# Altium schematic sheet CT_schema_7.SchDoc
size 454 x 430 mm
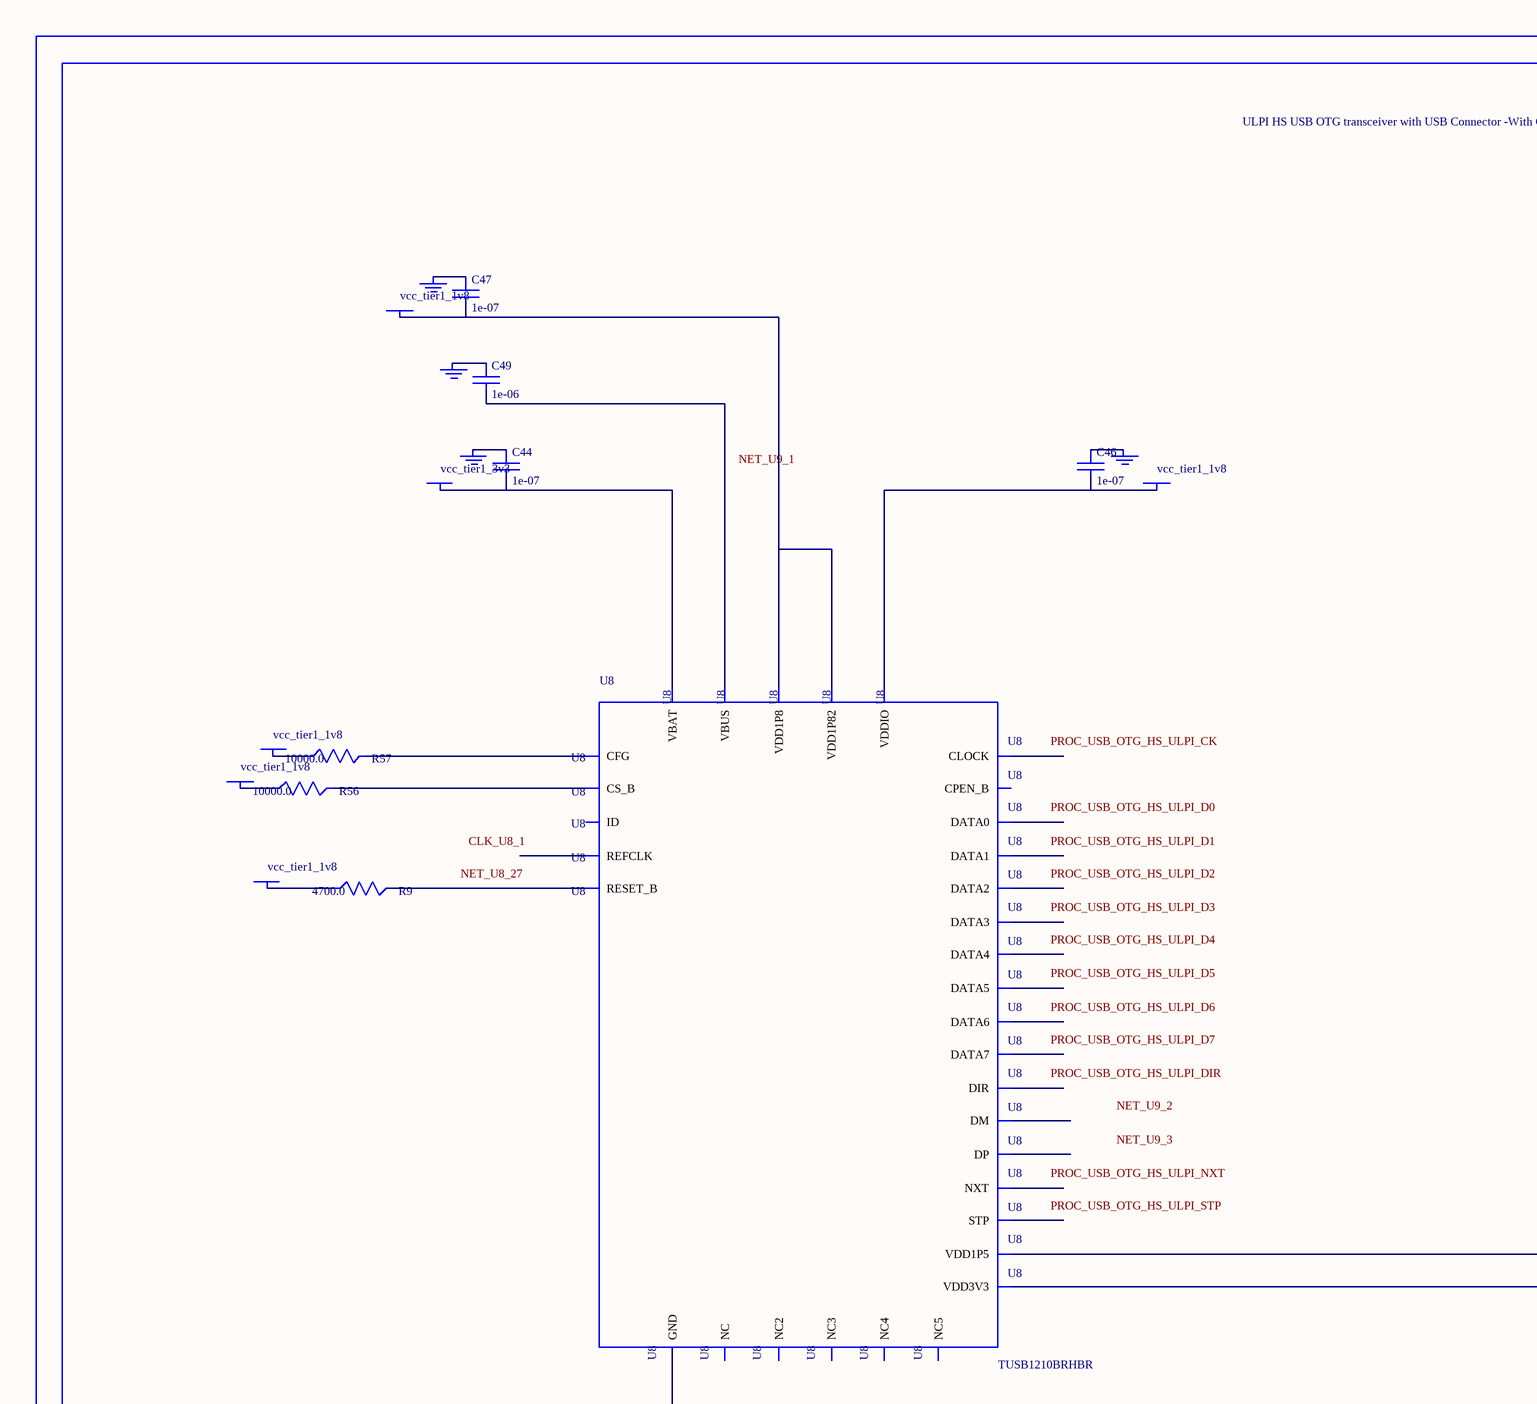
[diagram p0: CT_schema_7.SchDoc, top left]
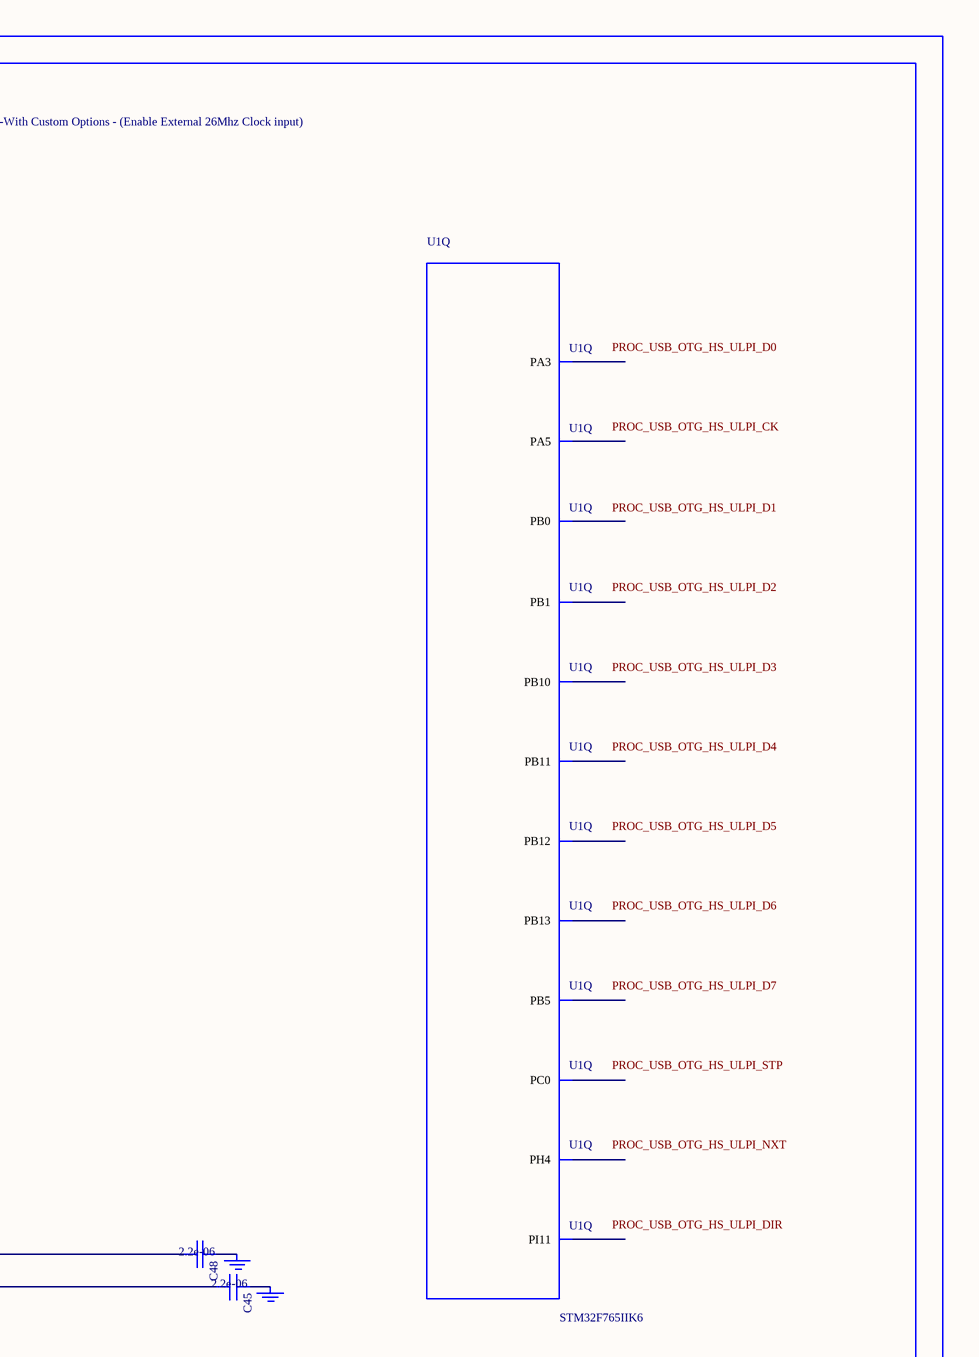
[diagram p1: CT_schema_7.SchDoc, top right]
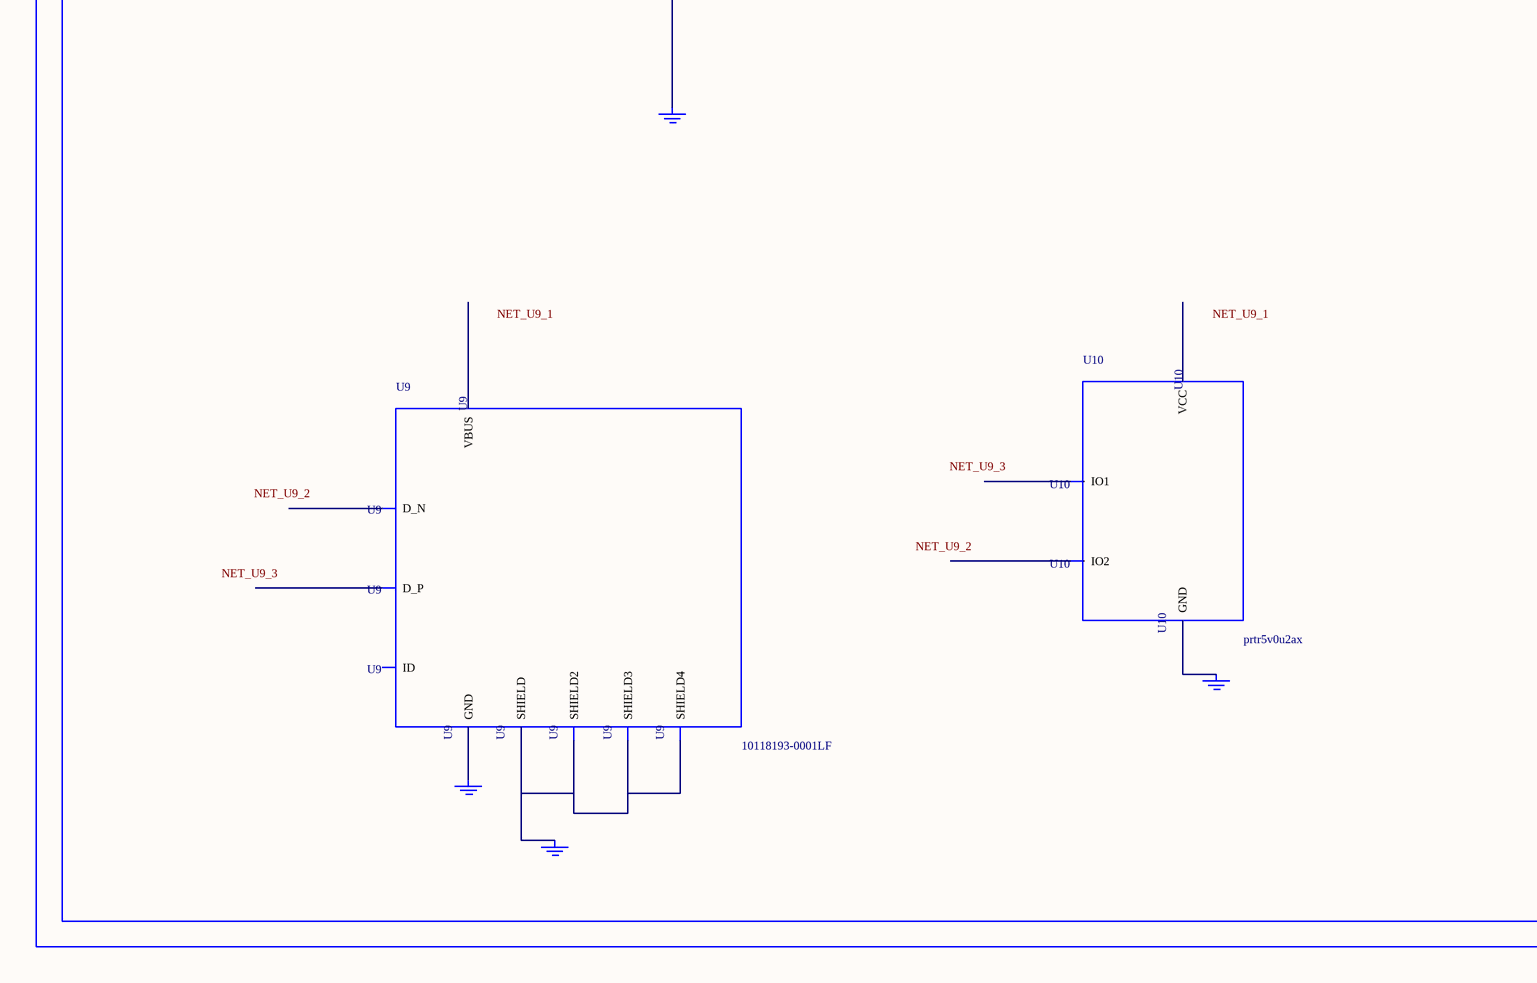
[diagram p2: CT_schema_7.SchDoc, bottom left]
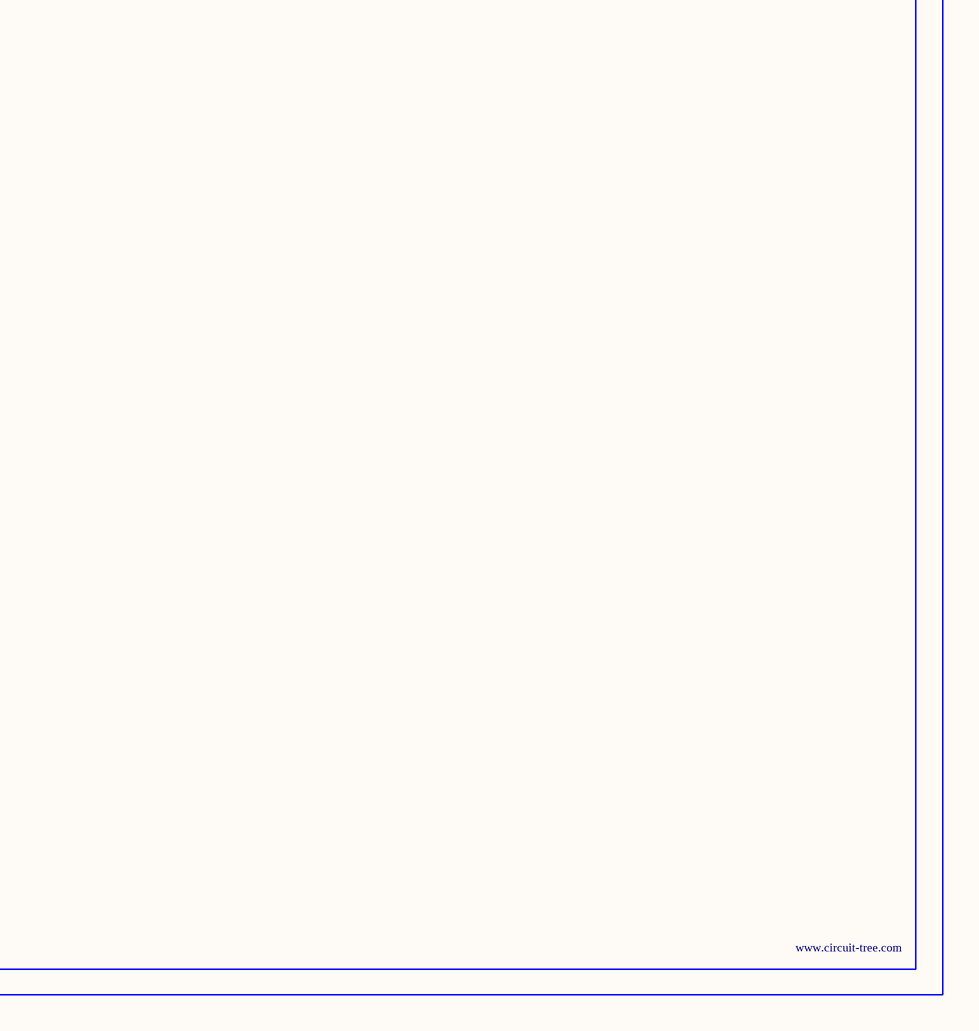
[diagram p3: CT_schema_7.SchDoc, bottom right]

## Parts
BORDER6  (no value)
C44  1e-07  [C0402]
C45  2.2e-06  [C0603]
C46  1e-07  [C0402]
C47  1e-07  [C0402]
C48  2.2e-06  [C0603]
C49  1e-06  [C0603]
GND_INSTANCE_6_0  (no value)
GND_INSTANCE_6_1  (no value)
GND_INSTANCE_6_2  (no value)
GND_INSTANCE_6_3  (no value)
GND_INSTANCE_6_4  (no value)
GND_INSTANCE_6_5  (no value)
GND_INSTANCE_6_6  (no value)
GND_INSTANCE_6_7  (no value)
GND_INSTANCE_6_8  (no value)
GND_INSTANCE_6_9  (no value)
POWER_INSTANCE_6_0  vcc_tier1_1v8
POWER_INSTANCE_6_1  vcc_tier1_1v8
POWER_INSTANCE_6_2  vcc_tier1_3v3
POWER_INSTANCE_6_3  vcc_tier1_1v8
POWER_INSTANCE_6_4  vcc_tier1_1v8
POWER_INSTANCE_6_5  vcc_tier1_1v8
R9  4700.0  [R0603]
R56  10000.0  [R0603]
R57  10000.0  [R0603]
U1  STM32F765IIK6  [UFBGA176_25]  (part Q of 17)
U8  TUSB1210BRHBR  [RHB32_3P45X3P45]
U9  10118193-0001LF  [FCI_10118193-0001LF]
U10  prtr5v0u2ax  [SOT143B]

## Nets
NetC44_1: C44.1 GND_INSTANCE_6_2.0(GND)
NetC44_2: C44.2 POWER_INSTANCE_6_2.0(PWR) U8.21(VBAT)
NetC45_1: C45.1 GND_INSTANCE_6_1.0(GND)
NetC45_2: C45.2 U8.20(VDD3V3)
NetC46_1: C46.1 GND_INSTANCE_6_5.0(GND)
NetC46_2: C46.2 POWER_INSTANCE_6_4.0(PWR) U8.32(VDDIO)
NetC47_1: C47.1 GND_INSTANCE_6_4.0(GND)
NetC47_2: C47.2 POWER_INSTANCE_6_3.0(PWR) U8.28(VDD1P8) U8.30(VDD1P82)
NetC48_1: C48.1 GND_INSTANCE_6_0.0(GND)
NetC48_2: C48.2 U8.12(VDD1P5)
NetC49_1: C49.1 GND_INSTANCE_6_3.0(GND)
NetC49_2: C49.2 U8.22(VBUS)
NetGND_INSTANCE_6_6_0: GND_INSTANCE_6_6.0(GND) U8.33(GND)
NetGND_INSTANCE_6_7_0: GND_INSTANCE_6_7.0(GND) U9.6(SHIELD) U9.7(SHIELD2) U9.8(SHIELD3) U9.9(SHIELD4)
NetGND_INSTANCE_6_8_0: GND_INSTANCE_6_8.0(GND) U9.5(GND)
NetGND_INSTANCE_6_9_0: GND_INSTANCE_6_9.0(GND) U10.1(GND)
NetPOWER_INSTANCE_6_0_0: POWER_INSTANCE_6_0.0(PWR) R56.1
NetPOWER_INSTANCE_6_1_0: POWER_INSTANCE_6_1.0(PWR) R57.1
NetPOWER_INSTANCE_6_5_0: POWER_INSTANCE_6_5.0(PWR) R9.1
NetR9_2: R9.2 U8.27(RESET_B)
NetR56_2: R56.2 U8.11(CS_B)
NetR57_2: R57.2 U8.14(CFG)

Not connected (* = marked no-connect by the designer): U1 A6(PB5) E4(PI11) H4(PH4) M2(PC0) P4(PA5) P12(PB12) P13(PB13) R2(PA3) R4(PB1) R5(PB0) R12(PB10) R13(PB11); U8 1(REFCLK) 2(NXT) 3(DATA0) 4(DATA1) 5(DATA2) 6(DATA3) 7(DATA4) 8(NC) 9(DATA5) 10(DATA6) 13(DATA7) 15(NC2) 16(NC3) 17(CPEN_B) 18(DP) 19(DM) 23(ID) 24(NC4) 25(NC5) 26(CLOCK) 29(STP) 31(DIR); U9 1(VBUS) 2(D_N) 3(D_P) 4(ID); U10 2(IO1) 3(IO2) 4(VCC)

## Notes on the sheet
- Labels drawn without touching a wire or pin: CLK_U8_1, NET_U8_27, NET_U9_1, NET_U9_2, NET_U9_3, PROC_USB_OTG_HS_ULPI_CK, PROC_USB_OTG_HS_ULPI_D0, PROC_USB_OTG_HS_ULPI_D1, PROC_USB_OTG_HS_ULPI_D2, PROC_USB_OTG_HS_ULPI_D3, PROC_USB_OTG_HS_ULPI_D4, PROC_USB_OTG_HS_ULPI_D5, PROC_USB_OTG_HS_ULPI_D6, PROC_USB_OTG_HS_ULPI_D7, PROC_USB_OTG_HS_ULPI_DIR, PROC_USB_OTG_HS_ULPI_NXT, PROC_USB_OTG_HS_ULPI_STP

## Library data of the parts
BORDER6 = BORDER_PAGE6
C44 C46 C47 = C0402C104K3RACTU
C45 C48 = C0603C225K8RACTU
C49 = C0603C105K3RACTU
GND_INSTANCE_6_0-GND_INSTANCE_6_9 = GND
POWER_INSTANCE_6_0-POWER_INSTANCE_6_5 = PWR
R9 = RC0603JR-074K7L
R56 R57 = RC0603JR-0710KL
